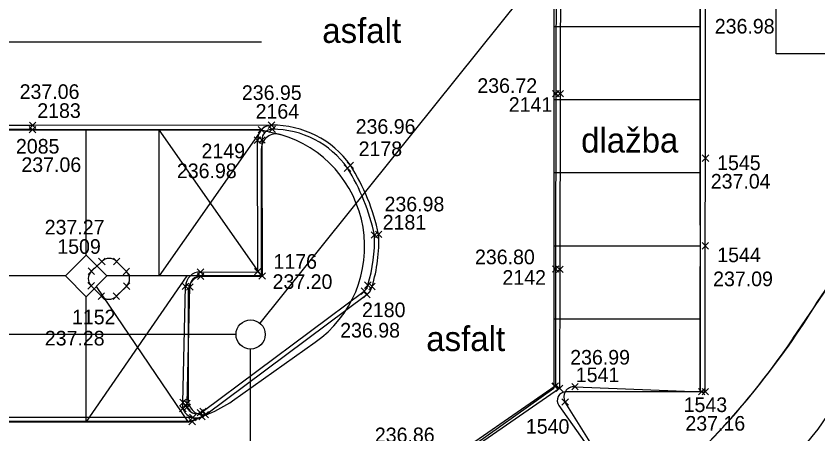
# Model space of a CAD drawing. Extents: x -264165 to -263733, y -1242319 to -1242245.
# Drawn here: x -263825.46 to -263798.04, y -1242287.38 to -1242273.09 of the extents above; entities that cross this region are included whole.
import ezdxf

# ---------------------------------------------------------------- set-up
doc = ezdxf.new("R2010")
doc.units = 0
for name, color, linetype in [('KFA_BOD_CISLO', 7, 'Continuous'), ('KFA_BOD_SYMBOL', 7, 'Continuous'), ('KFA_BOD_VYSKA', 7, 'Continuous'), ('KFA_SO_20-2_OBRUBNIKY_DOLNA_HRANA', 7, 'Continuous'), ('KFA_SO_20-2_OBRUBNIKY_HORNA_HRANA', 7, 'Continuous'), ('POPIS', 7, 'Continuous'), ('PROJEKT_OBRUBNIKY_KOMUNIKACIE', 7, 'Continuous'), ('PROJEKT_TDZ_VODOROVNE', 7, 'Continuous'), ('SITUACIA_DSP_2D', 7, 'Continuous')]:
    doc.layers.add(name, color=color, linetype=linetype)

msp = doc.modelspace()

# ---------------------------------------------------------------- linework, layer by layer
at = {"layer": 'KFA_BOD_SYMBOL'}
for p, q in [((-263807.112, -1242275.853), (-263806.891, -1242275.633)), ((-263806.891, -1242275.853), (-263807.112, -1242275.633)), ((-263806.965, -1242275.856), (-263806.744, -1242275.634)), ((-263806.744, -1242275.856), (-263806.965, -1242275.634)), ((-263825.007, -1242276.943), (-263824.785, -1242276.721)), ((-263824.785, -1242276.943), (-263825.007, -1242276.721)), ((-263816.838, -1242276.934), (-263816.617, -1242276.714)), ((-263816.617, -1242276.934), (-263816.838, -1242276.714)), ((-263816.815, -1242277.076), (-263816.594, -1242276.855)), ((-263816.594, -1242277.076), (-263816.815, -1242276.855)), ((-263825.014, -1242277.086), (-263824.793, -1242276.866)), ((-263824.793, -1242277.086), (-263825.014, -1242276.866)), ((-263817.185, -1242277.09), (-263816.964, -1242276.87)), ((-263816.964, -1242277.09), (-263817.185, -1242276.87)), ((-263817.317, -1242277.448), (-263817.095, -1242277.227)), ((-263817.095, -1242277.448), (-263817.317, -1242277.227)), ((-263817.166, -1242277.438), (-263816.945, -1242277.218)), ((-263816.945, -1242277.438), (-263817.166, -1242277.218)), ((-263801.997, -1242278.062), (-263801.775, -1242277.842)), ((-263801.775, -1242278.062), (-263801.997, -1242277.842)), ((-263814.242, -1242278.404), (-263814.02, -1242278.183)), ((-263814.02, -1242278.404), (-263814.242, -1242278.183)), ((-263814.141, -1242278.306), (-263813.92, -1242278.086)), ((-263813.92, -1242278.306), (-263814.141, -1242278.086)), ((-263813.318, -1242280.691), (-263813.096, -1242280.47)), ((-263813.096, -1242280.691), (-263813.318, -1242280.47)), ((-263813.175, -1242280.667), (-263812.954, -1242280.445)), ((-263812.954, -1242280.667), (-263813.175, -1242280.445)), ((-263802.002, -1242281.062), (-263801.78, -1242280.84)), ((-263801.78, -1242281.062), (-263802.002, -1242280.84)), ((-263822.642, -1242281.596), (-263822.421, -1242281.374)), ((-263822.421, -1242281.596), (-263822.642, -1242281.374)), ((-263822.133, -1242281.596), (-263821.912, -1242281.376)), ((-263821.912, -1242281.596), (-263822.133, -1242281.376)), ((-263823, -1242281.93), (-263822.779, -1242281.708)), ((-263822.779, -1242281.93), (-263823, -1242281.708)), ((-263821.8, -1242281.938), (-263821.579, -1242281.718)), ((-263821.579, -1242281.938), (-263821.8, -1242281.718)), ((-263819.268, -1242281.958), (-263819.046, -1242281.737)), ((-263819.046, -1242281.958), (-263819.268, -1242281.737)), ((-263817.308, -1242281.947), (-263817.087, -1242281.725)), ((-263817.087, -1242281.947), (-263817.308, -1242281.725)), ((-263807.122, -1242281.856), (-263806.9, -1242281.634)), ((-263806.9, -1242281.856), (-263807.122, -1242281.634)), ((-263806.976, -1242281.865), (-263806.755, -1242281.644)), ((-263806.755, -1242281.865), (-263806.976, -1242281.644)), ((-263819.263, -1242282.102), (-263819.041, -1242281.88)), ((-263819.041, -1242282.102), (-263819.263, -1242281.88)), ((-263817.16, -1242282.095), (-263816.938, -1242281.873)), ((-263816.938, -1242282.095), (-263817.16, -1242281.873)), ((-263823.006, -1242282.431), (-263822.785, -1242282.21)), ((-263822.785, -1242282.431), (-263823.006, -1242282.21)), ((-263821.794, -1242282.441), (-263821.573, -1242282.22)), ((-263821.573, -1242282.441), (-263821.794, -1242282.22)), ((-263819.778, -1242282.447), (-263819.557, -1242282.225)), ((-263819.557, -1242282.447), (-263819.778, -1242282.225)), ((-263819.632, -1242282.468), (-263819.41, -1242282.247)), ((-263819.41, -1242282.468), (-263819.632, -1242282.247)), ((-263813.546, -1242282.404), (-263813.324, -1242282.184)), ((-263813.324, -1242282.404), (-263813.546, -1242282.184)), ((-263813.399, -1242282.451), (-263813.177, -1242282.231)), ((-263813.177, -1242282.451), (-263813.399, -1242282.231)), ((-263822.656, -1242282.782), (-263822.435, -1242282.562)), ((-263822.435, -1242282.782), (-263822.656, -1242282.562)), ((-263822.144, -1242282.781), (-263821.924, -1242282.559)), ((-263821.924, -1242282.781), (-263822.144, -1242282.559)), ((-263813.665, -1242282.61), (-263813.443, -1242282.389)), ((-263813.443, -1242282.61), (-263813.665, -1242282.389)), ((-263813.579, -1242282.728), (-263813.357, -1242282.508)), ((-263813.357, -1242282.728), (-263813.579, -1242282.508)), ((-263807.131, -1242285.852), (-263806.91, -1242285.63)), ((-263806.91, -1242285.852), (-263807.131, -1242285.63)), ((-263807.139, -1242285.865), (-263806.918, -1242285.644)), ((-263806.918, -1242285.865), (-263807.139, -1242285.644)), ((-263806.989, -1242285.936), (-263806.768, -1242285.715)), ((-263806.768, -1242285.936), (-263806.989, -1242285.715)), ((-263806.459, -1242285.879), (-263806.238, -1242285.657)), ((-263806.238, -1242285.879), (-263806.459, -1242285.657)), ((-263802.129, -1242286.051), (-263801.908, -1242285.829)), ((-263801.908, -1242286.051), (-263802.129, -1242285.829)), ((-263802.003, -1242286.049), (-263801.782, -1242285.828)), ((-263801.782, -1242286.049), (-263802.003, -1242285.828)), ((-263806.796, -1242286.403), (-263806.575, -1242286.181)), ((-263806.575, -1242286.403), (-263806.796, -1242286.181)), ((-263819.871, -1242286.63), (-263819.649, -1242286.409)), ((-263819.649, -1242286.63), (-263819.871, -1242286.409)), ((-263819.867, -1242286.42), (-263819.645, -1242286.198)), ((-263819.645, -1242286.42), (-263819.867, -1242286.198)), ((-263819.726, -1242286.454), (-263819.504, -1242286.234)), ((-263819.504, -1242286.454), (-263819.726, -1242286.234)), ((-263819.725, -1242286.582), (-263819.503, -1242286.36)), ((-263819.503, -1242286.582), (-263819.725, -1242286.36)), ((-263819.53, -1242286.93), (-263819.308, -1242286.708)), ((-263819.308, -1242286.93), (-263819.53, -1242286.708)), ((-263819.274, -1242286.765), (-263819.052, -1242286.543)), ((-263819.052, -1242286.765), (-263819.274, -1242286.543)), ((-263819.214, -1242286.897), (-263818.992, -1242286.676)), ((-263818.992, -1242286.897), (-263819.214, -1242286.676)), ((-263819.181, -1242286.718), (-263818.959, -1242286.497)), ((-263818.959, -1242286.718), (-263819.181, -1242286.497)), ((-263819.101, -1242286.838), (-263818.879, -1242286.617)), ((-263818.879, -1242286.838), (-263819.101, -1242286.617)), ((-263819.55, -1242287.069), (-263819.329, -1242286.849)), ((-263819.329, -1242287.069), (-263819.55, -1242286.849))]:
    msp.add_line(p, q, dxfattribs=at)
at = {"layer": 'KFA_SO_20-2_OBRUBNIKY_DOLNA_HRANA'}
msp.add_line((-263817.198, -1242281.836), (-263817.206, -1242277.337), dxfattribs=at)
for points in [[(-263806.994, -1242271.026), (-263807.002, -1242275.743), (-263807.011, -1242281.745), (-263807.02, -1242285.741), (-263807.029, -1242285.754), (-263811.073, -1242288.555), (-263815.133, -1242291.369), (-263816.759, -1242292.501), (-263817.492, -1242292.982)], [(-263806.84, -1242270.884), (-263806.855, -1242275.745), (-263806.866, -1242281.754), (-263806.878, -1242285.825), (-263810.985, -1242288.673), (-263815.032, -1242291.478), (-263816.678, -1242292.619), (-263817.431, -1242293.129)], [(-263816.727, -1242276.824), (-263824.896, -1242276.832), (-263841.932, -1242276.838), (-263860.969, -1242276.825), (-263872.991, -1242276.822), (-263881, -1242276.818), (-263897.019, -1242276.831), (-263905.035, -1242276.846), (-263913.057, -1242276.848), (-263917.557, -1242276.899)], [(-263817.074, -1242276.98), (-263824.904, -1242276.976), (-263831.918, -1242276.976), (-263841.931, -1242276.979), (-263850.949, -1242276.976), (-263860.958, -1242276.969), (-263872.991, -1242276.965), (-263880.996, -1242276.964), (-263889.006, -1242276.968), (-263897.017, -1242276.976), (-263905.035, -1242276.99), (-263913.048, -1242276.994), (-263917.092, -1242277.009)], [(-263819.157, -1242281.847), (-263817.198, -1242281.836)], [(-263819.76, -1242286.519), (-263819.756, -1242286.309), (-263819.667, -1242282.336)], [(-263819.103, -1242286.786), (-263818.99, -1242286.727), (-263813.468, -1242282.618)], [(-263819.103, -1242286.786), (-263819.439, -1242286.959), (-263828.996, -1242286.962), (-263838.005, -1242286.965), (-263845.009, -1242286.967), (-263853.017, -1242286.968), (-263861.032, -1242286.966), (-263868.037, -1242286.96), (-263877.037, -1242286.952), (-263886.053, -1242286.951), (-263895.068, -1242286.953), (-263904.067, -1242286.955), (-263910.084, -1242286.961), (-263917.346, -1242286.958)], [(-263819.419, -1242286.819), (-263828.995, -1242286.822), (-263838.007, -1242286.821), (-263845.022, -1242286.826), (-263853.012, -1242286.818), (-263861.03, -1242286.825), (-263868.034, -1242286.816), (-263877.043, -1242286.812), (-263886.05, -1242286.81), (-263895.064, -1242286.807), (-263904.07, -1242286.816), (-263910.08, -1242286.821), (-263917.062, -1242286.824)]]:
    msp.add_lwpolyline(points, dxfattribs=at)
for centre, major_axis, ratio, start_param, end_param in [((-263816.713, -1242277.316), (-0.493, 0.007), 0.998656, 4.754947, 6.340777), ((-263816.689, -1242280.086), (-3.013, 1.255), 0.999232, 4.154509, 5.118327), ((-263819.937, -1242281.995), (-1.771, 6.806), 0.998447, 4.664219, 5.028829), ((-263818.332, -1242280.801), (0.659, 5.249), 0.996882, 4.541527, 4.88325), ((-263819.172, -1242282.341), (0.177, 0.462), 0.999862, 0.334864, 1.925632), ((-263813.759, -1242282.232), (0.264, 0.407), 0.997615, 4.364767, 5.060011), ((-263819.309, -1242286.35), (0.352, -0.33), 0.999624, 4.254194, 5.906626)]:
    msp.add_ellipse(centre, major_axis=major_axis, ratio=ratio, start_param=start_param, end_param=end_param, dxfattribs=at)
at = {"layer": 'KFA_SO_20-2_OBRUBNIKY_HORNA_HRANA'}
for p, q in [((-263817.056, -1242277.328), (-263817.049, -1242281.984)), ((-263822.531, -1242281.485), (-263822.889, -1242281.819)), ((-263821.689, -1242281.828), (-263822.023, -1242281.486)), ((-263822.895, -1242282.32), (-263822.546, -1242282.672)), ((-263822.034, -1242282.67), (-263821.683, -1242282.33))]:
    msp.add_line(p, q, dxfattribs=at)
for points in [[(-263806.349, -1242285.768), (-263802.019, -1242285.94), (-263801.893, -1242285.938), (-263801.891, -1242280.951), (-263801.886, -1242277.952), (-263801.882, -1242272.951), (-263801.89, -1242270.939), (-263802.035, -1242270.942), (-263805.994, -1242270.993), (-263806.398, -1242270.99)], [(-263819.152, -1242281.991), (-263817.049, -1242281.984)], [(-263819.614, -1242286.471), (-263819.615, -1242286.344), (-263819.521, -1242282.357)], [(-263819.163, -1242286.654), (-263819.07, -1242286.607), (-263813.554, -1242282.499)], [(-263809.779, -1242293.921), (-263804.32, -1242290.11), (-263804.578, -1242289.676), (-263806.686, -1242286.292)]]:
    msp.add_lwpolyline(points, dxfattribs=at)
for centre, major_axis, ratio, start_param, end_param in [((-263816.708, -1242277.314), (0.221, -0.27), 0.999554, 2.444805, 4.067697), ((-263816.683, -1242280.081), (-2.988, 0.888), 0.99971, 4.041842, 5.007956), ((-263820.116, -1242282.043), (-1.733, 6.852), 0.999129, 4.673397, 5.024188), ((-263818.277, -1242280.781), (0.914, 5.027), 0.992715, 4.590369, 4.930442), ((-263822.278, -1242281.734), (-0.331, -0.13), 0.999487, 3.538313, 5.13144), ((-263822.645, -1242282.072), (-0.004, -0.352), 0.999816, 3.920946, 5.503832), ((-263821.926, -1242282.082), (0.257, 0.234), 0.999872, 4.747625, 6.36402), ((-263819.16, -1242282.352), (-0.268, -0.242), 0.999148, 3.955685, 5.562393), ((-263813.749, -1242282.249), (0.284, 0.142), 0.999734, 4.911122, 5.6763), ((-263822.291, -1242282.412), (0.358, -0.066), 0.9986, 4.118636, 5.677436), ((-263806.378, -1242286.12), (-0.146, -0.321), 0.999003, 3.486151, 5.650017), ((-263819.307, -1242286.361), (0.104, -0.309), 0.999868, 4.731058, 6.4166)]:
    msp.add_ellipse(centre, major_axis=major_axis, ratio=ratio, start_param=start_param, end_param=end_param, dxfattribs=at)
at = {"layer": 'PROJEKT_OBRUBNIKY_KOMUNIKACIE'}
for p, q in [((-263798.899, -1242284.125), (-263780.363, -1242256.915)), ((-263807.068, -1242270.982), (-263807.068, -1242285.823)), ((-263802.068, -1242280.24), (-263802.068, -1242271.654)), ((-263917.08, -1242276.982), (-263817.068, -1242276.982)), ((-263817.068, -1242276.982), (-263816.429, -1242277.14)), ((-263817.068, -1242281.982), (-263817.068, -1242277.62)), ((-263802.068, -1242285.947), (-263802.068, -1242281.654)), ((-263817.068, -1242281.982), (-263819.068, -1242281.982)), ((-263819.568, -1242286.231), (-263819.568, -1242282.482)), ((-263818.06, -1242286.248), (-263815.232, -1242284.248)), ((-263817.19, -1242292.982), (-263807.068, -1242285.823)), ((-263819.568, -1242286.982), (-263818.882, -1242286.695)), ((-263819.568, -1242286.982), (-263917.08, -1242286.982))]:
    msp.add_line(p, q, dxfattribs=at)
for points in [[(-263798.064, -1242282.882), (-263794.987, -1242278.383), (-263796.968, -1242278.382), (-263796.968, -1242274.382), (-263799.468, -1242274.382), (-263799.468, -1242270.382), (-263791.968, -1242270.382), (-263791.968, -1242266.382), (-263796.968, -1242266.382), (-263796.968, -1242260.382), (-263791.968, -1242260.382), (-263791.968, -1242258.382), (-263799.468, -1242258.382), (-263799.468, -1242265.987), (-263802.068, -1242265.987)], [(-263802.068, -1242265.987), (-263802.068, -1242270.24), (-263802.068, -1242270.947), (-263802.068, -1242271.654), (-263802.068, -1242273.447), (-263802.068, -1242275.947), (-263802.068, -1242278.447), (-263802.068, -1242280.24), (-263802.068, -1242281.654), (-263802.068, -1242283.447), (-263802.068, -1242285.947), (-263806.656, -1242285.943)], [(-263823.068, -1242281.275), (-263822.361, -1242281.982), (-263823.068, -1242282.689), (-263823.775, -1242281.982), (-263823.068, -1242281.275)], [(-263806.901, -1242286.416), (-263804.349, -1242290.024), (-263802.552, -1242288.44)]]:
    msp.add_lwpolyline(points, dxfattribs=at)
for centre, radius, start, end in [((-263816.568, -1242277.62), 0.5, 73.8446, 180), ((-263817.542, -1242280.982), 4, 305.2702, 73.8446), ((-263819.068, -1242282.482), 0.5, 90, 180), ((-263821.806, -1242268.304), 27.86, 313.7192, 328.4502), ((-263820.069, -1242269.909), 25.5, 305.2702, 326.1165), ((-263806.656, -1242286.243), 0.3, 89.9436, 215.2702), ((-263819.068, -1242286.231), 0.5, 180, 291.8332), ((-263820.369, -1242282.982), 4, 291.8332, 305.2702)]:
    msp.add_arc(centre, radius, start, end, dxfattribs=at)
at = {"layer": 'PROJEKT_TDZ_VODOROVNE'}
for p, q in [((-263807.068, -1242273.447), (-263802.068, -1242273.447)), ((-263817.068, -1242273.982), (-263917.477, -1242273.982)), ((-263807.068, -1242275.947), (-263802.068, -1242275.947)), ((-263823.068, -1242281.275), (-263823.068, -1242276.982)), ((-263820.568, -1242281.982), (-263820.568, -1242276.982)), ((-263817.068, -1242276.982), (-263820.568, -1242281.982)), ((-263817.068, -1242281.982), (-263820.568, -1242276.982)), ((-263807.068, -1242278.447), (-263802.068, -1242278.447)), ((-263807.068, -1242280.947), (-263802.068, -1242280.947)), ((-263823.775, -1242281.982), (-263829.861, -1242281.982)), ((-263823.068, -1242286.982), (-263819.614, -1242281.982)), ((-263818.068, -1242281.982), (-263822.361, -1242281.982)), ((-263819.568, -1242286.982), (-263822.714, -1242282.336)), ((-263823.068, -1242286.982), (-263823.068, -1242282.689)), ((-263807.068, -1242283.447), (-263802.068, -1242283.447))]:
    msp.add_line(p, q, dxfattribs=at)
msp.add_lwpolyline([(-263816.072, -1242319.185), (-263814.291, -1242315.804), (-263813.06, -1242301.353), (-263812.968, -1242299.181), (-263802.618, -1242291.831), (-263801.478, -1242290.893), (-263800.257, -1242289.755), (-263799.049, -1242288.464), (-263798.027, -1242287.218), (-263780.363, -1242261.313)], dxfattribs=at)
msp.add_arc((-263817.542, -1242280.982), 4, 83.1966, 90, dxfattribs=at)
at = {"layer": 'SITUACIA_DSP_2D'}
for p, q in [((-263798.899, -1242284.125), (-263780.363, -1242256.915)), ((-263807.38, -1242271.45), (-263817.128, -1242283.593)), ((-263802.068, -1242280.24), (-263802.068, -1242271.654)), ((-263817.068, -1242281.982), (-263817.068, -1242277.62)), ((-263802.068, -1242285.947), (-263802.068, -1242281.654)), ((-263817.068, -1242281.982), (-263819.068, -1242281.982)), ((-263819.568, -1242286.231), (-263819.568, -1242282.482)), ((-263817.941, -1242283.982), (-263870.324, -1242283.982)), ((-263817.941, -1242283.982), (-263870.324, -1242283.982)), ((-263818.06, -1242286.248), (-263815.232, -1242284.248)), ((-263817.441, -1242292.492), (-263817.441, -1242284.482))]:
    msp.add_line(p, q, dxfattribs=at)
for points in [[(-263798.064, -1242282.882), (-263794.987, -1242278.383), (-263796.968, -1242278.382), (-263796.968, -1242274.382), (-263799.468, -1242274.382), (-263799.468, -1242270.382), (-263791.968, -1242270.382), (-263791.968, -1242266.382), (-263796.968, -1242266.382), (-263796.968, -1242260.382), (-263791.968, -1242260.382), (-263791.968, -1242258.382), (-263799.468, -1242258.382), (-263799.468, -1242265.987), (-263802.068, -1242265.987)], [(-263802.068, -1242265.987), (-263802.068, -1242270.24), (-263802.068, -1242270.947), (-263802.068, -1242271.654), (-263802.068, -1242273.447), (-263802.068, -1242275.947), (-263802.068, -1242278.447), (-263802.068, -1242280.24), (-263802.068, -1242280.24), (-263802.068, -1242281.654), (-263802.068, -1242283.447), (-263802.068, -1242285.947), (-263806.656, -1242285.943)], [(-263806.901, -1242286.416), (-263804.349, -1242290.024), (-263802.552, -1242288.44)]]:
    msp.add_lwpolyline(points, dxfattribs=at)
msp.add_lwpolyline([(-263823.068, -1242281.275), (-263822.361, -1242281.982), (-263823.068, -1242282.689), (-263823.775, -1242281.982)], close=True, dxfattribs=at)
msp.add_circle((-263817.441, -1242283.982), 0.5, dxfattribs=at)
for centre, radius, start, end in [((-263816.568, -1242277.62), 0.5, 73.8446, 180), ((-263817.542, -1242280.982), 4, 305.2702, 73.8446), ((-263819.068, -1242282.482), 0.5, 90, 180), ((-263821.806, -1242268.304), 27.86, 313.7192, 328.4502), ((-263820.069, -1242269.909), 25.5, 305.2702, 326.1165), ((-263806.656, -1242286.243), 0.3, 89.9436, 215.2702), ((-263819.068, -1242286.231), 0.5, 180, 291.8332), ((-263820.369, -1242282.982), 4, 291.8332, 305.2702)]:
    msp.add_arc(centre, radius, start, end, dxfattribs=at)

# ---------------------------------------------------------------- texts
at = {"layer": 'KFA_BOD_CISLO'}
for s, p in [('2141', (-263808.613, -1242276.368)), ('2183', (-263824.738, -1242276.576)), ('2164', (-263817.271, -1242276.602)), ('2085', (-263825.468, -1242277.796)), ('2178', (-263813.748, -1242277.882)), ('2149', (-263819.121, -1242277.955)), ('1545', (-263801.487, -1242278.36)), ('2181', (-263812.925, -1242280.394)), ('1509', (-263824.053, -1242281.224)), ('1176', (-263816.66, -1242281.735)), ('1544', (-263801.483, -1242281.509)), ('2142', (-263808.829, -1242282.282)), ('2180', (-263813.633, -1242283.389)), ('1152', (-263823.551, -1242283.635)), ('1541', (-263806.321, -1242285.612)), ('1543', (-263802.632, -1242286.635)), ('1540', (-263808.028, -1242287.375))]:
    msp.add_text(s, height=0.5, dxfattribs=at).set_placement(p)
at = {"layer": 'KFA_BOD_VYSKA'}
for s, p in [('236.98', (-263801.567, -1242273.69)), ('237.06', (-263825.341, -1242275.927)), ('236.95', (-263817.741, -1242275.962)), ('236.72', (-263809.688, -1242275.721)), ('236.96', (-263813.849, -1242277.118)), ('237.06', (-263825.281, -1242278.425)), ('236.98', (-263819.963, -1242278.635)), ('237.04', (-263801.704, -1242278.993)), ('236.98', (-263812.862, -1242279.772)), ('237.27', (-263824.484, -1242280.562)), ('236.80', (-263809.768, -1242281.58)), ('237.20', (-263816.69, -1242282.425)), ('237.09', (-263801.624, -1242282.33)), ('236.98', (-263814.378, -1242284.087)), ('237.28', (-263824.48, -1242284.358)), ('236.99', (-263806.512, -1242285.012)), ('237.16', (-263802.572, -1242287.271)), ('236.86', (-263813.193, -1242287.666))]:
    msp.add_text(s, height=0.5, dxfattribs=at).set_placement(p)
at = {"layer": 'POPIS'}
for s, p in [('asfalt', (-263814.991, -1242274.011)), ('dlažba', (-263806.139, -1242277.76)), ('asfalt', (-263811.435, -1242284.549))]:
    msp.add_text(s, height=0.8438, dxfattribs=at).set_placement(p)

doc.saveas('drawing.dxf')
